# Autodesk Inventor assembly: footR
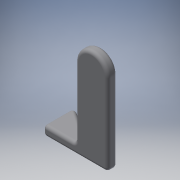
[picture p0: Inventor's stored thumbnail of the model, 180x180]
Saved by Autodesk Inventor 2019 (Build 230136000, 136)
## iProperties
Created: 2020-09
Part Number: footR
Material: 一般
Document SubType Name: Assembly
Designer: kikut
Author: kikut
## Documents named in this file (2)
- F:\openFOAM\basilisk\oversetmeshfootR\CAD\footR.iam
- F:\openFOAM\basilisk\oversetmeshfootR\CAD\footR.ipt
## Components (1 placed, 1 different names)
1. footR:1 — メイト:1, メイト:2
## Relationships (2: Mate 2)
- メイト:1 [Mate]: footR:1
- メイト:2 [Mate]: footR:1
